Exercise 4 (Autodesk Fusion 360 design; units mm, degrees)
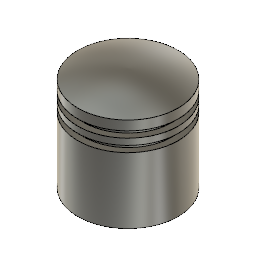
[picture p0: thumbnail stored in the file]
sketch "Sketch1" plane through (0, 0, 0) normal (0, 1, 0) x axis (1, 0, 0)
  line L1 (0, -38.2597) -> (0, 0)
  line L2 (36.7046, 0) -> (0, 0)
  line L3 (13, -10) -> (13, 0)
  line L4 (16, 0) -> (13, 0)
  line L5 (16, -21) -> (16, 0)
  line L6 (14, -21) -> (16, -21)
  line L7 (14, -23) -> (14, -21)
  line L8 (16, -23) -> (14, -23)
  line L9 (16, -25) -> (16, -23)
  line L10 (14, -25) -> (16, -25)
  line L11 (14, -27) -> (14, -25)
  line L12 (16, -27) -> (14, -27)
  line L13 (16, -30) -> (16, -27)
  line L14 (0, -25) -> (0, -33)
  line L15 (10, -25) -> (0, -25)
  line L16 (10, -10) -> (10, -25)
  line L17 (13, -10) -> (10, -10)
  arc A1 centre (-1.0915, 16.9881) radius 50 clockwise from (16, -30) to (0, -33)
  point P1 (0, 0)
  point P2 (0, 0)
  point P4 (0, 0)
  point P6 (13, 0)
  point P8 (16, 0)
  point P18 (0, -33)
  point P20 (0, -25)
  point P7 (13, -10)
  point P9 (16, -21)
  point P16 (16, -27)
  point P17 (16, -30)
  point P21 (10, -25)
  point P22 (10, -10)
  coincident P1 P2
  vertical L1
  coincident P1 P4
  perpendicular L1 L2
  coincident L2 P6
  perpendicular L2 L3
  coincident L2 P8
  perpendicular L4 L5
  perpendicular L5 L6
  perpendicular L6 L7
  perpendicular L7 L8
  perpendicular L8 L9
  perpendicular L9 L10
  perpendicular L10 L11
  perpendicular L11 L12
  perpendicular L12 L13
  equal L7 L11
  equal L7 L9
  equal L8 L10
  collinear L5 L9
  collinear L5 L13
  coincident L1 P18
  coincident L1 P20
  parallel L1 L14
  perpendicular L1 L15
  perpendicular L15 L16
  perpendicular L3 L17
  dimension "d1" = 26
  dimension "d2" distance P6 P7 = 10
  dimension "d3" = 32
  dimension "d4" distance P8 P9 = 21
  dimension "d5" distance L6 L8 = 2
  dimension "d6" distance L5 L7 = 2
  dimension "d7" distance P16 P17 = 3
  dimension "d8" radius A1 = 50
  dimension "d9" distance P18 L15 = 8
  dimension "d10" distance P21 P22 = 15
  dimension "d11" = 20
revolve "Revolve1" sketch "Sketch1" AlongAngle 360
